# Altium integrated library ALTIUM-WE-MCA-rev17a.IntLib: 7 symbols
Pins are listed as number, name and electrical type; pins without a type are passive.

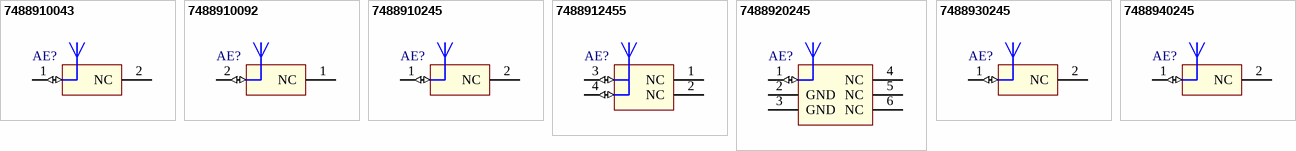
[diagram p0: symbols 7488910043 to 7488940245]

## 7488910043
designator AE?
WE-MCA Multilayer Chip Antenna, 423-443MHz; Part Number: 7488910043; Impedance: 50 Ohm
footprint 7488910043 (WE-MCA Multilayer Chip Antenna)
pins: 1 Feed (io), 2 NC

## 7488910092
designator AE?
WE-MCA Multilayer Chip Antenna, 868-960MHz; Part Number: 7488910092; Impedance: 50 Ohm
footprint 7488910092 (WE-MCA Multilayer Chip Antenna)
pins: 1 NC, 2 Feed (io)

## 7488910245
designator AE?
WE-MCA Multilayer Chip Antenna, 2400-2500MHz; Part Number: 7488910245; Impedance: 50 Ohm
footprint 7488910245 (WE-MCA Multilayer Chip Antenna)
pins: 1 Feed (io), 2 NC

## 7488912455
designator AE?
WE-MCA Multilayer Chip Dual Antenna, 2400-2500MHz, 4900-5875MHz; Part Number: 7488912455; Impedance: 50 Ohm
footprint 7488912455 (WE-MCA Multilayer Chip Antenna)
pins: 1 NC, 2 NC, 3 Feed_Low Band (io), 4 Feed_High Band (io)

## 7488920245
designator AE?
WE-MCA Multilayer Chip Antenna, 2400-2500MHz; Part Number: 7488920245; Impedance: 50 Ohm
footprint 7488920245 (WE-MCA Multilayer Chip Antenna)
pins: 1 Feed (io), 2 GND, 3 GND, 4 NC, 5 NC, 6 NC

## 7488930245
designator AE?
WE-MCA Multilayer Chip Antenna, 2400-2500MHz; Part Number: 7488930245; Impedance: 50 Ohm
footprint 7488930245 (WE-MCA Multilayer Chip Antenna)
pins: 1 Feed (io), 2 NC

## 7488940245
designator AE?
WE-MCA Multilayer Chip Antenna, 2400-2500MHz; Part Number: 7488940245; Impedance: 50 Ohm
footprint 7488940245 (WE-MCA Multilayer Chip Antenna)
pins: 1 Feed (io), 2 NC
